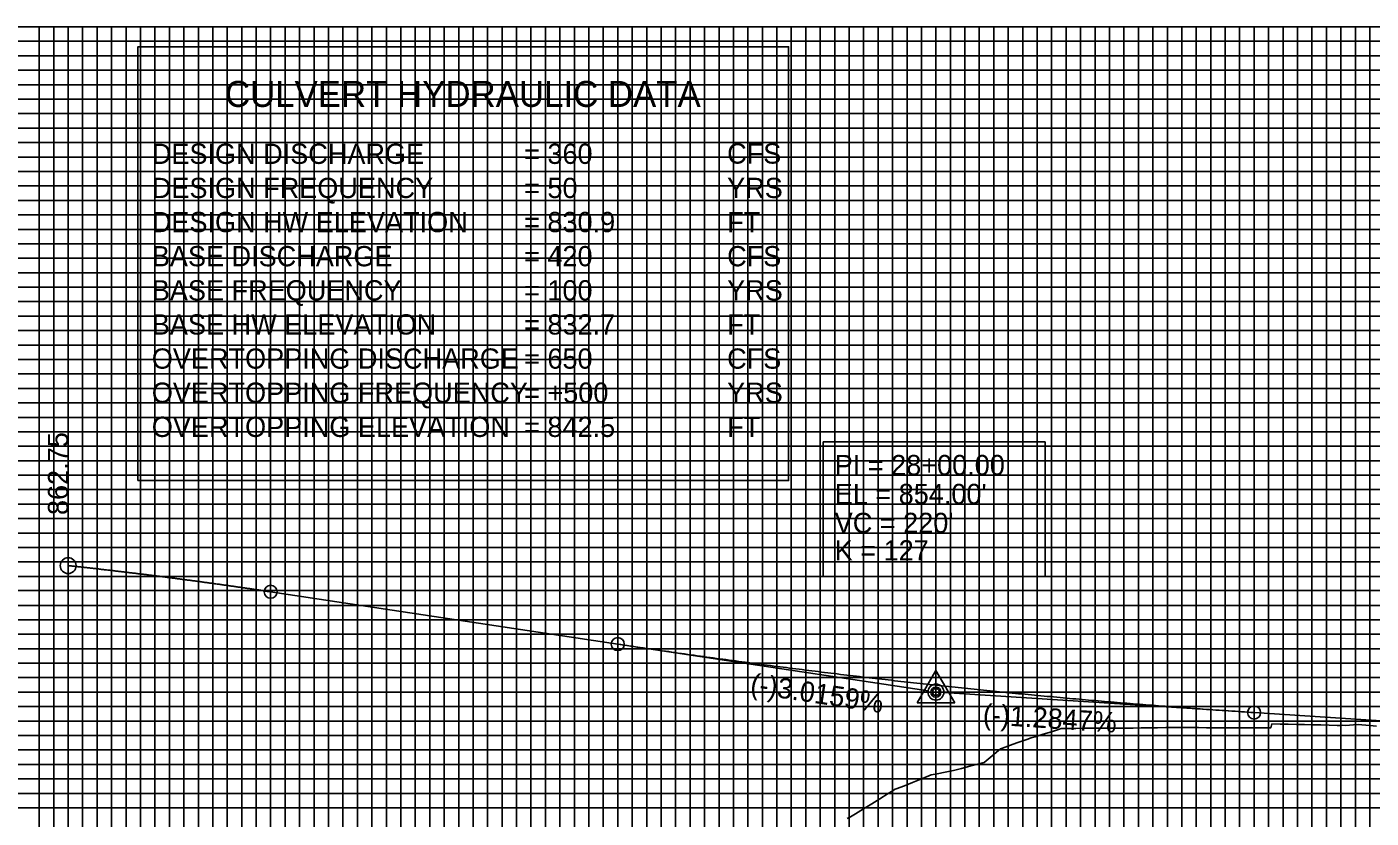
# Model space of a CAD drawing. Extents: x 570622 to 580296, y -55533 to -48575.
# Drawn here: x 570874.4 to 571339.1, y -53055.6 to -52782.1 of the extents above; entities that cross this region are included whole.
import ezdxf

# ---------------------------------------------------------------- set-up
doc = ezdxf.new("R2010")
doc.units = 0
for name, color, linetype in [('Exist Vertical Profile Ground Line', 7, 'Continuous'), ('Prop Grid Mask', 7, 'Continuous'), ('Prop PFL Culvert Hydraulic Data Label CELL', 7, 'Continuous'), ('Prop PFL VPI Symbol CELL', 7, 'Continuous'), ('Prop Vertical Profile Curve Label', 7, 'Continuous'), ('Prop Vertical Profile Grade', 7, 'Continuous'), ('Prop Vertical Profile Grade Label', 7, 'Continuous'), ('Prop VPI Label', 7, 'Continuous'), ('Sheet DOT Grid CELL', 7, 'Continuous'), ('Sheet Layout Profile Border Port 2', 7, 'Continuous'), ('Sheet Profile CELL', 7, 'Continuous'), ('Sheet Profile Grid Major CELL', 7, 'Continuous'), ('Sheet Profile Grid Middle CELL', 7, 'Continuous'), ('Sheet Profile Grid Minor CELL', 7, 'Continuous')]:
    doc.layers.add(name, color=color, linetype=linetype)

msp = doc.modelspace()

# ---------------------------------------------------------------- linework, layer by layer
at = {"layer": 'Exist Vertical Profile Ground Line'}
for points in [[(571160.84, -53054.18), (571163.67, -53052.45), (571166.49, -53050.7), (571169.31, -53048.92), (571172.14, -53047.12), (571173.28, -53046.38), (571174.65, -53045.65), (571174.96, -53045.53), (571177.78, -53044.42), (571180.61, -53043.29), (571183.43, -53042.14), (571186.26, -53040.96), (571186.99, -53040.64), (571189.08, -53040.26), (571191.9, -53039.71), (571194.73, -53039.13), (571197.55, -53038.43), (571200.38, -53037.71), (571203.2, -53036.96), (571205.34, -53036.37), (571206.02, -53035.82), (571208.85, -53033.49), (571211.02, -53031.67), (571211.67, -53031.44), (571214.49, -53030.39), (571216.68, -53029.57), (571217.32, -53029.36), (571220.14, -53028.41), (571221.65, -53027.89), (571222.97, -53027.49), (571225.79, -53026.62), (571228.61, -53025.73), (571231.44, -53024.82), (571231.95, -53024.65), (571234.26, -53024.62), (571237.08, -53024.59), (571239.91, -53024.55), (571241.97, -53024.52), (571242.73, -53024.53), (571245.56, -53024.57), (571245.96, -53024.57), (571248.38, -53024.55), (571251.2, -53024.52), (571254.03, -53024.5), (571256.85, -53024.46), (571259.68, -53024.43), (571262.5, -53024.4), (571265.32, -53024.36), (571268.15, -53024.32), (571270.97, -53024.27), (571271.87, -53024.26), (571273.79, -53024.28), (571276.62, -53024.31), (571279.44, -53024.34), (571282.27, -53024.37), (571284.39, -53024.39), (571285.09, -53024.39), (571287.91, -53024.38), (571290.74, -53024.37), (571293.56, -53024.36), (571294.92, -53024.35), (571296.38, -53024.36), (571299.21, -53024.37), (571302.03, -53024.37), (571304.49, -53024.38), (571304.86, -53023.04), (571307.68, -53023.11), (571310.5, -53023.17), (571313.33, -53023.24), (571316.15, -53023.3), (571318.98, -53023.36), (571321.8, -53023.42), (571324.62, -53023.49), (571327.45, -53023.55), (571328.54, -53023.57), (571329.12, -53023.53), (571330.27, -53023.59), (571333.09, -53023.36), (571334.78, -53023.21), (571335.92, -53023.32), (571338.74, -53023.6), (571341.06, -53023.83)], [(571158.02, -53055.74), (571159.14, -53055.21), (571160.84, -53054.18)]]:
    msp.add_lwpolyline(points, dxfattribs=at)
at = {"layer": 'Prop Grid Mask'}
for points in [[(570912.77, -52938.93), (571137.77, -52938.93), (571137.77, -52788.93), (570912.77, -52788.93)], [(571149.72, -52925.54), (571226.45, -52925.54), (571226.45, -52972.09), (571149.72, -52972.09)]]:
    msp.add_lwpolyline(points, close=True, dxfattribs=at)
at = {"layer": 'Prop PFL VPI Symbol CELL'}
for p, q in [((571188.68, -53004.57), (571182.23, -53015.77)), ((571188.68, -53004.57), (571195.18, -53015.77)), ((571182.23, -53015.77), (571195.18, -53015.77))]:
    msp.add_line(p, q, dxfattribs=at)
for radius in [1.75, 1.2]:
    msp.add_circle((571188.69, -53012.05), radius, dxfattribs=at)
at = {"layer": 'Prop Vertical Profile Curve Label'}
for centre in [(570958.69, -52977.37), (571078.69, -52995.47), (571298.69, -53019.12)]:
    msp.add_circle(centre, 2.25, dxfattribs=at)
at = {"layer": 'Prop Vertical Profile Grade'}
for p, q in [((570958.69, -52977.37), (571078.69, -52995.47)), ((571298.69, -53019.12), (571355.93, -53022.8))]:
    msp.add_line(p, q, dxfattribs=at)
for points in [[(570888.69, -52968.32), (570890.09, -52968.47), (570891.49, -52968.62), (570892.89, -52968.78), (570894.29, -52968.93), (570895.69, -52969.09), (570897.09, -52969.24), (570898.49, -52969.4), (570899.89, -52969.56), (570901.29, -52969.73), (570902.69, -52969.89), (570904.09, -52970.05), (570905.49, -52970.22), (570906.89, -52970.38), (570908.29, -52970.55), (570909.69, -52970.72), (570911.09, -52970.89), (570912.49, -52971.06), (570913.89, -52971.23), (570915.29, -52971.4), (570916.69, -52971.58), (570918.09, -52971.75), (570919.49, -52971.93), (570920.89, -52972.11), (570922.29, -52972.29), (570923.69, -52972.47), (570925.09, -52972.65), (570926.49, -52972.83), (570927.89, -52973.02), (570929.29, -52973.2), (570930.69, -52973.39), (570932.09, -52973.58), (570933.49, -52973.77), (570934.89, -52973.96), (570936.29, -52974.15), (570937.69, -52974.34), (570939.09, -52974.53), (570940.49, -52974.73), (570941.89, -52974.92), (570943.29, -52975.12), (570944.69, -52975.32), (570946.09, -52975.52), (570947.49, -52975.72), (570948.89, -52975.92), (570950.29, -52976.13), (570951.69, -52976.33), (570953.09, -52976.54), (570954.49, -52976.74), (570955.89, -52976.95), (570957.29, -52977.16), (570958.69, -52977.37)], [(571078.69, -52995.47), (571083.09, -52996.13), (571087.49, -52996.78), (571091.89, -52997.42), (571096.29, -52998.06), (571100.69, -52998.69), (571105.09, -52999.31), (571109.49, -52999.92), (571113.89, -53000.53), (571118.29, -53001.13), (571122.69, -53001.72), (571127.09, -53002.3), (571131.49, -53002.88), (571135.89, -53003.45), (571140.29, -53004.01), (571144.69, -53004.56), (571149.09, -53005.11), (571153.49, -53005.65), (571157.89, -53006.18), (571162.29, -53006.7), (571166.69, -53007.21), (571171.09, -53007.72), (571175.49, -53008.22), (571179.89, -53008.71), (571184.29, -53009.2), (571188.69, -53009.67), (571193.09, -53010.14), (571197.49, -53010.61), (571201.89, -53011.06), (571206.29, -53011.51), (571210.69, -53011.94), (571215.09, -53012.38), (571219.49, -53012.8), (571223.89, -53013.21), (571228.29, -53013.62), (571232.69, -53014.02), (571237.09, -53014.42), (571241.49, -53014.8), (571245.89, -53015.18), (571250.29, -53015.55), (571254.69, -53015.91), (571259.09, -53016.27), (571263.49, -53016.62), (571267.89, -53016.96), (571272.29, -53017.29), (571276.69, -53017.61), (571281.09, -53017.93), (571285.49, -53018.24), (571289.89, -53018.54), (571294.29, -53018.83), (571298.69, -53019.12)]]:
    msp.add_spline(points, degree=3, dxfattribs=at)
at = {"layer": 'Prop VPI Label'}
for p, q in [((571078.69, -52995.47), (571185.97, -53011.64)), ((571298.69, -53019.12), (571191.43, -53012.23))]:
    msp.add_line(p, q, dxfattribs=at)
for centre in [(570888.69, -52968.32), (571188.69, -53012.05)]:
    msp.add_circle(centre, 2.75, dxfattribs=at)
at = {"layer": 'Sheet DOT Grid CELL'}
for p, q in [((570788.69, -52782.05), (572288.57, -52782.05)), ((570888.69, -52782.05), (570888.69, -53282.05)), ((570938.69, -52782.05), (570938.69, -53282.05)), ((570988.69, -52782.05), (570988.69, -53282.05)), ((571038.69, -52782.05), (571038.69, -53282.05)), ((571088.69, -52782.05), (571088.69, -53282.05)), ((571138.69, -52782.05), (571138.69, -53282.05)), ((571188.69, -52782.05), (571188.69, -53282.05)), ((571238.69, -52782.05), (571238.69, -53282.05)), ((571288.69, -52782.05), (571288.69, -53282.05)), ((571338.69, -52782.05), (571338.69, -53282.05)), ((570788.69, -52832.05), (572288.57, -52832.05)), ((570788.69, -52882.05), (572288.57, -52882.05)), ((570788.69, -52932.05), (572288.57, -52932.05)), ((570788.69, -52982.05), (572288.57, -52982.05)), ((570788.69, -53032.05), (572288.57, -53032.05))]:
    msp.add_line(p, q, dxfattribs=at)
at = {"layer": 'Sheet Layout Profile Border Port 2'}
msp.add_lwpolyline([(570838.69, -52782.05), (572238.69, -52782.05), (572238.69, -53282.05), (570838.69, -53282.05)], close=True, dxfattribs=at)
at = {"layer": 'Sheet Profile CELL'}
msp.add_line((570788.69, -52782.05), (572288.69, -52782.05), dxfattribs=at)
at = {"layer": 'Sheet Profile Grid Major CELL'}
msp.add_line((571288.69, -52782.05), (571338.69, -52782.05), dxfattribs=at)
for points in [[(570838.69, -52782.05), (570838.69, -53282.05), (570888.69, -53282.05), (570888.69, -52782.05), (570938.69, -52782.05), (570938.69, -53282.05), (570988.69, -53282.05), (570988.69, -52782.05), (571038.69, -52782.05), (571038.69, -53282.05), (571088.69, -53282.05), (571088.69, -52782.05), (571138.69, -52782.05), (571138.69, -53282.05), (571188.69, -53282.05), (571188.69, -52782.05), (571238.69, -52782.05), (571238.69, -53282.05), (571288.69, -53282.05), (571288.69, -52782.05), (571338.69, -52782.05), (571338.69, -53282.05), (571388.69, -53282.05)], [(572288.69, -52832.05), (570788.69, -52832.05)], [(572288.69, -52882.05), (570788.69, -52882.05), (570788.69, -52932.05), (572288.69, -52932.05)], [(572288.69, -52982.05), (570788.69, -52982.05), (570788.69, -53032.05), (572288.69, -53032.05)]]:
    msp.add_lwpolyline(points, dxfattribs=at)
at = {"layer": 'Sheet Profile Grid Middle CELL'}
for points in [[(570813.69, -52782.05), (570863.69, -52782.05), (570863.69, -53282.05), (570913.69, -53282.05), (570913.69, -52782.05), (570963.69, -52782.05), (570963.69, -53282.05), (571013.69, -53282.05), (571013.69, -52782.05), (571063.69, -52782.05), (571063.69, -53282.05), (571113.69, -53282.05), (571113.69, -52782.05), (571163.69, -52782.05), (571163.69, -53282.05), (571213.69, -53282.05), (571213.69, -52782.05), (571263.69, -52782.05), (571263.69, -53282.05), (571313.69, -53282.05), (571313.69, -52782.05), (571363.69, -52782.05)], [(570788.69, -52807.05), (572288.69, -52807.05)], [(572288.69, -52857.05), (570788.69, -52857.05), (570788.69, -52907.05), (572288.69, -52907.05)], [(572288.69, -52957.05), (570788.69, -52957.05), (570788.69, -53007.05), (572288.69, -53007.05)]]:
    msp.add_lwpolyline(points, dxfattribs=at)
at = {"layer": 'Sheet Profile Grid Minor CELL'}
for p, q in [((570838.69, -52787.05), (572238.69, -52787.05)), ((572238.69, -52792.05), (570838.69, -52792.05)), ((570838.69, -52797.05), (572238.69, -52797.05)), ((572238.69, -52802.05), (570838.69, -52802.05)), ((570838.69, -52812.05), (572238.69, -52812.05)), ((572238.69, -52817.05), (570838.69, -52817.05)), ((570838.69, -52822.05), (572238.69, -52822.05)), ((572238.69, -52827.05), (570838.69, -52827.05)), ((570838.69, -52837.05), (572238.69, -52837.05)), ((572238.69, -52842.05), (570838.69, -52842.05)), ((570838.69, -52847.05), (572238.69, -52847.05)), ((572238.69, -52852.05), (570838.69, -52852.05)), ((570838.69, -52862.05), (572238.69, -52862.05)), ((572238.69, -52867.05), (570838.69, -52867.05)), ((570838.69, -52872.05), (572238.69, -52872.05)), ((572238.69, -52877.05), (570838.69, -52877.05)), ((570838.69, -52887.05), (572238.69, -52887.05)), ((572238.69, -52892.05), (570838.69, -52892.05)), ((570838.69, -52897.05), (572238.69, -52897.05)), ((572238.69, -52902.05), (570838.69, -52902.05)), ((570838.69, -52912.05), (572238.69, -52912.05)), ((572238.69, -52917.05), (570838.69, -52917.05)), ((570838.69, -52922.05), (572238.69, -52922.05)), ((572238.69, -52927.05), (570838.69, -52927.05)), ((570838.69, -52937.05), (572238.69, -52937.05)), ((572238.69, -52942.05), (570838.69, -52942.05)), ((570838.69, -52947.05), (572238.69, -52947.05)), ((572238.69, -52952.05), (570838.69, -52952.05)), ((570838.69, -52962.05), (572238.69, -52962.05)), ((572238.69, -52967.05), (570838.69, -52967.05)), ((570838.69, -52972.05), (572238.69, -52972.05)), ((572238.69, -52977.05), (570838.69, -52976.9)), ((570838.69, -52987.05), (572238.69, -52987.05)), ((572238.69, -52992.05), (570838.69, -52992.05)), ((570838.69, -52997.05), (572238.69, -52997.05)), ((572238.69, -53002.05), (570838.69, -53002.05)), ((570838.69, -53012.05), (572238.69, -53012.05)), ((572238.69, -53017.05), (570838.69, -53017.05)), ((570838.69, -53022.05), (572238.69, -53022.05)), ((572238.69, -53027.05), (570838.69, -53027.05)), ((570838.69, -53037.05), (572238.69, -53037.05)), ((572238.69, -53042.05), (570838.69, -53042.05)), ((570838.69, -53047.05), (572238.69, -53047.05)), ((572238.69, -53052.05), (570838.69, -53052.05))]:
    msp.add_line(p, q, dxfattribs=at)
for points in [[(570873.69, -52782.05), (570878.69, -52782.05), (570878.69, -53282.05)], [(570883.69, -53282.05), (570883.69, -52782.05), (570893.69, -52782.05), (570893.69, -53282.05)], [(570898.69, -53282.05), (570898.69, -52782.05), (570903.69, -52782.05), (570903.69, -53282.05)], [(570908.69, -53282.05), (570908.69, -52782.05), (570918.69, -52782.05), (570918.69, -53282.05)], [(570923.69, -53282.05), (570923.69, -52782.05), (570928.69, -52782.05), (570928.69, -53282.05)], [(570933.69, -53282.05), (570933.69, -52782.05), (570943.69, -52782.05), (570943.69, -53282.05)], [(570948.69, -53282.05), (570948.69, -52782.05), (570953.69, -52782.05), (570953.69, -53282.05)], [(570958.69, -53282.05), (570958.69, -52782.05), (570968.69, -52782.05), (570968.69, -53282.05)], [(570973.69, -53282.05), (570973.69, -52782.05), (570978.69, -52782.05), (570978.69, -53282.05)], [(570983.69, -53282.05), (570983.69, -52782.05), (570993.69, -52782.05), (570993.69, -53282.05)], [(570998.69, -53282.05), (570998.69, -52782.05), (571003.69, -52782.05), (571003.69, -53282.05)], [(571008.69, -53282.05), (571008.69, -52782.05), (571018.69, -52782.05), (571018.69, -53282.05)], [(571023.69, -53282.05), (571023.69, -52782.05), (571028.69, -52782.05), (571028.69, -53282.05)], [(571033.69, -53282.05), (571033.69, -52782.05), (571043.69, -52782.05), (571043.69, -53282.05)], [(571048.69, -53282.05), (571048.69, -52782.05), (571053.69, -52782.05), (571053.69, -53282.05)], [(571058.69, -53282.05), (571058.69, -52782.05), (571068.69, -52782.05), (571068.69, -53282.05)], [(571073.69, -53282.05), (571073.69, -52782.05), (571078.69, -52782.05), (571078.69, -53282.05)], [(571083.69, -53282.05), (571083.69, -52782.05), (571093.69, -52782.05), (571093.69, -53282.05)], [(571098.69, -53282.05), (571098.69, -52782.05), (571103.69, -52782.05), (571103.69, -53282.05)], [(571108.69, -53282.05), (571108.69, -52782.05), (571118.69, -52782.05), (571118.69, -53282.05)], [(571123.69, -53282.05), (571123.69, -52782.05), (571128.69, -52782.05), (571128.69, -53282.05)], [(571133.69, -53282.05), (571133.69, -52782.05), (571143.69, -52782.05), (571143.69, -53282.05)], [(571148.69, -53282.05), (571148.69, -52782.05), (571153.69, -52782.05), (571153.69, -53282.05)], [(571158.69, -53282.05), (571158.69, -52782.05), (571168.69, -52782.05), (571168.69, -53282.05)], [(571173.69, -53282.05), (571173.69, -52782.05), (571178.69, -52782.05), (571178.69, -53282.05)], [(571183.69, -53282.05), (571183.69, -52782.05), (571193.69, -52782.05), (571193.69, -53282.05)], [(571198.69, -53282.05), (571198.69, -52782.05), (571203.69, -52782.05), (571203.69, -53282.05)], [(571208.69, -53282.05), (571208.69, -52782.05), (571218.69, -52782.05), (571218.69, -53282.05)], [(571223.69, -53282.05), (571223.69, -52782.05), (571228.69, -52782.05), (571228.69, -53282.05)], [(571233.69, -53282.05), (571233.69, -52782.05), (571243.69, -52782.05), (571243.69, -53282.05)], [(571248.69, -53282.05), (571248.69, -52782.05), (571253.69, -52782.05), (571253.69, -53282.05)], [(571258.69, -53282.05), (571258.69, -52782.05), (571268.69, -52782.05), (571268.69, -53282.05)], [(571273.69, -53282.05), (571273.69, -52782.05), (571278.69, -52782.05), (571278.69, -53282.05)], [(571283.69, -53282.05), (571283.69, -52782.05), (571293.69, -52782.05), (571293.69, -53282.05)], [(571298.69, -53282.05), (571298.69, -52782.05), (571303.69, -52782.05), (571303.69, -53282.05)], [(571308.69, -53282.05), (571308.69, -52782.05), (571318.69, -52782.05), (571318.69, -53282.05)], [(571323.69, -53282.05), (571323.69, -52782.05), (571328.69, -52782.05), (571328.69, -53282.05)], [(571333.69, -53282.05), (571333.69, -52782.05), (571343.69, -52782.05)]]:
    msp.add_lwpolyline(points, dxfattribs=at)

# ---------------------------------------------------------------- texts
at = {"layer": 'Prop PFL Culvert Hydraulic Data Label CELL'}
for s, height, p in [('CULVERT HYDRAULIC DATA', 9, (570942.87, -52809.73)), ('DESIGN DISCHARGE', 6.9999, (570917.6, -52829.43)), ('= 360', 7, (571046.3, -52829.43)), ('CFS', 7, (571116.5, -52829.33)), ('DESIGN FREQUENCY', 6.9999, (570917.6, -52841.23)), ('= 50 ', 7, (571046.3, -52841.23)), ('YRS', 7, (571116.5, -52841.23)), ('DESIGN HW ELEVATION', 6.9999, (570917.6, -52853.03)), ('= 830.9', 7, (571046.3, -52853.03)), ('FT', 7, (571116.5, -52853.03)), ('BASE DISCHARGE', 6.9999, (570917.6, -52864.83)), ('= 420', 7, (571046.3, -52864.83)), ('CFS', 7, (571116.5, -52864.83)), ('BASE FREQUENCY', 6.9999, (570917.6, -52876.63)), ('= 100', 7, (571046.3, -52876.63)), ('YRS', 7, (571116.5, -52876.63)), ('BASE HW ELEVATION', 6.9999, (570917.6, -52888.43)), ('= 832.7', 7, (571046.3, -52888.43)), ('FT', 7, (571116.5, -52888.43)), ('OVERTOPPING DISCHARGE', 6.9999, (570917.6, -52900.23)), ('= 650', 7, (571046.3, -52900.23)), ('CFS', 7, (571116.5, -52900.23)), ('OVERTOPPING FREQUENCY', 6.9999, (570917.6, -52912.03)), ('= +500', 7, (571046.3, -52912.03)), ('YRS', 7, (571116.5, -52912.03)), ('OVERTOPPING ELEVATION', 6.9999, (570917.6, -52923.83)), ('= 842.5', 7, (571046.3, -52923.83)), ('FT', 7, (571116.5, -52923.83))]:
    msp.add_text(s, height=height, dxfattribs=at).set_placement(p)
at = {"layer": 'Prop Vertical Profile Curve Label'}
for s, p in [("VC = 220'", (571153.69, -52957.05)), ('K = 127', (571153.69, -52966.54))]:
    msp.add_text(s, height=7, dxfattribs=at).set_placement(p)
at = {"layer": 'Prop Vertical Profile Grade Label'}
for s, rotation, p in [('(-)3.0159%', 351.4247, (571124.21, -53012.45)), ('(-)1.2847%', 356.3245, (571204.76, -53023.11))]:
    msp.add_text(s, height=7, rotation=rotation, dxfattribs=at).set_placement(p)
at = {"layer": 'Prop VPI Label'}
msp.add_text('862.75', height=7, rotation=90, dxfattribs=at).set_placement((570888.69, -52950.82))
for s, p in [('PI = 28+00.00', (571153.69, -52937.05)), ("EL = 854.00'", (571153.69, -52947.05))]:
    msp.add_text(s, height=7, dxfattribs=at).set_placement(p)

doc.saveas('drawing.dxf')
